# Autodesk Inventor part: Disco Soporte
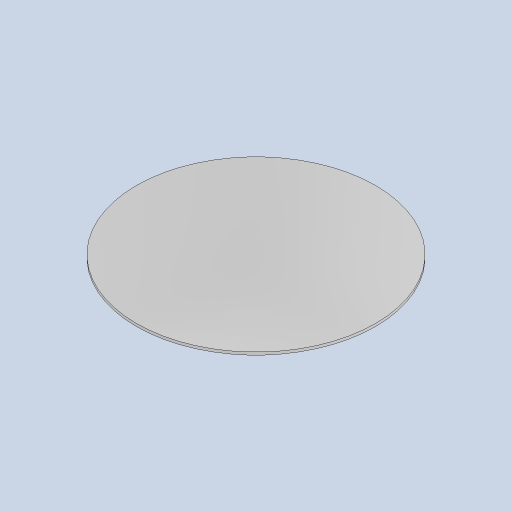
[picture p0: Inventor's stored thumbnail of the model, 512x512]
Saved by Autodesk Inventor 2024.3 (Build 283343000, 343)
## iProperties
Created: 2025-10
Part Number: Disco Soporte
Material: Acero inoxidable
Document SubType Name: Modeling
Designer: Asus
Density: 8 g/cm^3
Appearance: Pulido - Pequeña pirámide Moleteado
Author: Asus
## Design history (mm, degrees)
sketch "Boceto1"
  geometry: C1 r 90 at (0, 0); 1 further point
  constraints: 1 centre point, 1 coincident
  dimensions: "d0" = 180 diameter of C1
extrude "Extrusión1" new body sketch "Boceto1" distance "d1" = 2; taper "d2" = 0 deg
node "Sólido1"
